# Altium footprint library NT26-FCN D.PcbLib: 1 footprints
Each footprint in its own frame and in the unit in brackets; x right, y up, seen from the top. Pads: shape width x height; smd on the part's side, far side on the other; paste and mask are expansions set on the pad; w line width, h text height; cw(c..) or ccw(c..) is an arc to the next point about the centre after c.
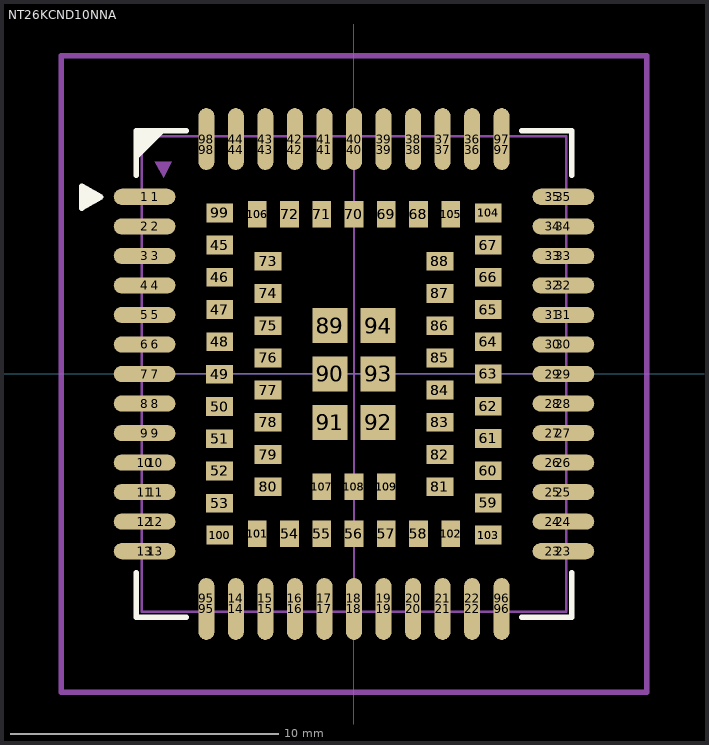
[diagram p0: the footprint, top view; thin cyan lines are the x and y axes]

## NT26KCND10NNA [mm]
height 2.54
pads (218):
  oval 2.3x0.6 smd mask+0.076: 1(-7.8,6.6) 2(-7.8,5.5) 3(-7.8,4.4) 4(-7.8,3.3) 5(-7.8,2.2) 6(-7.8,1.1) 7(-7.8,0) 8(-7.8,-1.1) 9(-7.8,-2.2) 10(-7.8,-3.3) 11(-7.8,-4.4) 12(-7.8,-5.5) 13(-7.8,-6.6) 23(7.8,-6.6) 24(7.8,-5.5) 25(7.8,-4.4) 26(7.8,-3.3) 27(7.8,-2.2) 28(7.8,-1.1) 29(7.8,0) 30(7.8,1.1) 31(7.8,2.2) 32(7.8,3.3) 33(7.8,4.4) 34(7.8,5.5) 35(7.8,6.6)
  oval 1.5x0.6 on Mech1 mask+0.076: 1(-7.4,6.6) 2(-7.4,5.5) 3(-7.4,4.4) 4(-7.4,3.3) 5(-7.4,2.2) 6(-7.4,1.1) 7(-7.4,0) 8(-7.4,-1.1) 9(-7.4,-2.2) 10(-7.4,-3.3) 11(-7.4,-4.4) 12(-7.4,-5.5) 13(-7.4,-6.6) 23(7.4,-6.6) 24(7.4,-5.5) 25(7.4,-4.4) 26(7.4,-3.3) 27(7.4,-2.2) 28(7.4,-1.1) 29(7.4,0) 30(7.4,1.1) 31(7.4,2.2) 32(7.4,3.3) 33(7.4,4.4) 34(7.4,5.5) 35(7.4,6.6)
  oval 0.6x2.3 smd mask+0.076: 14(-4.4,-8.75) 15(-3.3,-8.75) 16(-2.2,-8.75) 17(-1.1,-8.75) 18(0,-8.75) 19(1.1,-8.75) 20(2.2,-8.75) 21(3.3,-8.75) 22(4.4,-8.75) 36(4.4,8.75) 37(3.3,8.75) 38(2.2,8.75) 39(1.1,8.75) 40(0,8.75) 41(-1.1,8.75) 42(-2.2,8.75) 43(-3.3,8.75) 44(-4.4,8.75) 95(-5.5,-8.75) 96(5.5,-8.75) 97(5.5,8.75) 98(-5.5,8.75)
  oval 0.6x1.5 on Mech1 mask+0.076: 14(-4.4,-8.35) 15(-3.3,-8.35) 16(-2.2,-8.35) 17(-1.1,-8.35) 18(0,-8.35) 19(1.1,-8.35) 20(2.2,-8.35) 21(3.3,-8.35) 22(4.4,-8.35) 36(4.4,8.35) 37(3.3,8.35) 38(2.2,8.35) 39(1.1,8.35) 40(0,8.35) 41(-1.1,8.35) 42(-2.2,8.35) 43(-3.3,8.35) 44(-4.4,8.35) 95(-5.5,-8.35) 96(5.5,-8.35) 97(5.5,8.35) 98(-5.5,8.35)
  rect 1x0.7 smd: 45(-5,4.8) 46(-5,3.6) 47(-5,2.4) 48(-5,1.2) 49(-5.003,-0.011) 50(-5.003,-1.211) 51(-5.003,-2.411) 52(-5.003,-3.611) 53(-5.003,-4.811) 59(5,-4.8) 60(5,-3.6) 61(5,-2.4) 62(5,-1.2) 63(5,0) 64(5,1.2) 65(5,2.4) 66(5,3.6) 67(5,4.8) 73(-3.2,4.2) 74(-3.2,3) 75(-3.2,1.8) 76(-3.2,0.6) 77(-3.2,-0.6) 78(-3.2,-1.8) 79(-3.2,-3) 80(-3.2,-4.2) 81(3.2,-4.2) 82(3.2,-3) 83(3.2,-1.8) 84(3.2,-0.6) 85(3.2,0.6) 86(3.2,1.8) 87(3.2,3) 88(3.2,4.2) 99(-5,6) 100(-5,-6) 103(5,-6) 104(5,6)
  rect 1x0.7 on Mech1: 45(-5,4.8) 46(-5,3.6) 47(-5,2.4) 48(-5,1.2) 49(-5.003,-0.011) 50(-5.003,-1.211) 51(-5.003,-2.411) 52(-5.003,-3.611) 53(-5.003,-4.811) 59(5,-4.8) 60(5,-3.6) 61(5,-2.4) 62(5,-1.2) 63(5,0) 64(5,1.2) 65(5,2.4) 66(5,3.6) 67(5,4.8) 73(-3.2,4.2) 74(-3.2,3) 75(-3.2,1.8) 76(-3.2,0.6) 77(-3.2,-0.6) 78(-3.2,-1.8) 79(-3.2,-3) 80(-3.2,-4.2) 81(3.2,-4.2) 82(3.2,-3) 83(3.2,-1.8) 84(3.2,-0.6) 85(3.2,0.6) 86(3.2,1.8) 87(3.2,3) 88(3.2,4.2) 99(-5,6) 100(-5,-6) 103(5,-6) 104(5,6)
  rect 0.7x1 smd: 54(-2.4,-5.95) 55(-1.2,-5.95) 56(0,-5.95) 57(1.2,-5.95) 58(2.4,-5.95) 68(2.4,5.95) 69(1.2,5.95) 70(0,5.95) 71(-1.2,5.95) 72(-2.4,5.95) 101(-3.6,-5.95) 102(3.6,-5.95) 105(3.6,5.95) 106(-3.6,5.95) 107(-1.2,-4.2) 108(0,-4.2) 109(1.2,-4.2)
  rect 0.7x1 on Mech1: 54(-2.4,-5.95) 55(-1.2,-5.95) 56(0,-5.95) 57(1.2,-5.95) 58(2.4,-5.95) 68(2.4,5.95) 69(1.2,5.95) 70(0,5.95) 71(-1.2,5.95) 72(-2.4,5.95) 101(-3.6,-5.95) 102(3.6,-5.95) 105(3.6,5.95) 106(-3.6,5.95) 107(-1.2,-4.2) 108(0,-4.2) 109(1.2,-4.2)
  rect 1.3x1.3 smd: 89(-0.9,1.8) 90(-0.9,0) 91(-0.9,-1.8) 92(0.9,-1.8) 93(0.9,0) 94(0.9,1.8)
  rect 1.3x1.3 on Mech1: 89(-0.9,1.8) 90(-0.9,0) 91(-0.9,-1.8) 92(0.9,-1.8) 93(0.9,0) 94(0.9,1.8)
Top Overlay:
  region: -8.108,9.057 -8.097,7.973 -7.023,9.047
  region: -10.144,6.175 -9.42,6.59 -10.144,7.002
  lines w0.199: -8.108,-7.406 -8.108,-9.057 -6.25,-9.057 ; -8.108,7.406 -8.108,9.057 -6.25,9.057 ; 6.25,-9.057 8.108,-9.057 8.108,-7.406 ; 6.25,9.057 8.108,9.057 8.108,7.406 ; -10.144,6.175 -9.42,6.59 -10.144,7.002 -10.144,6.175
Mechanical 1:
  region: -7.08,7.308 -6.779,7.902 -7.426,7.902
  lines w0.051: -7.9,0 7.9,0 ; 0,-8.85 0,8.85
  lines w0.1: -7.9,-8.85 -7.9,8.85 7.9,8.85 7.9,-8.85 -7.9,-8.85
  lines w0.199: -10.9,-11.85 -10.9,-10.85 -10.9,10.85 -10.9,11.85 -9.9,11.85 -5.5,11.85 9.9,11.85 10.9,11.85 10.9,10.85 10.9,-10.85 10.9,-11.85 9.9,-11.85 -9.9,-11.85 -10.9,-11.85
